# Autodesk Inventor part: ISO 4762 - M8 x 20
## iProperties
Comments: To add or edit properties for Autodesk Inventor files, use iProperties.
Created: 2004-08
Part Number: ISO 4762 - M8 x 20
Vendor: Autodesk Inc.
Document SubType Name: Modeling
Designer: John Blackburn
Material: Default
Description: Hexagon Socket Head Cap Screw
Standard: ISO 4762
Size Designation: M8 x 20
Alert: To add or edit properties for Autodesk Inventor files, use iProperties.
Control State: 0
Master: False
Checked Out: False
Shininess: 64.0
Length Units: 11269
Angle Units: 11279
Time Units: 11290
Mass Units: 11283
Length Display Precision: 3
Angle Display Precision: 2
Compacted: True
EGR: 1
Density: 0.0
Volumn: 0.0
Area: 0.0
PropertySet Name: Model Information
Author: John Blackburn
Revision Number: 8
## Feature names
1. Body [Revolution]
2. Slot [Extrusion]
3. Fillet1
4. Chamfer1
